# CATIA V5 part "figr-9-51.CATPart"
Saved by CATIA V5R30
Part number: Part1
Bounding box of the stored display mesh (mm): x -121 to 121, y -90 to 90, z -40 to 40
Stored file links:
  D:\PROJECTS\CATIA V56R 2020\Resources\Parts File\c09_catia_v5_6r2020_prt\figr-9-51.CATPart
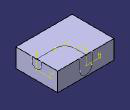
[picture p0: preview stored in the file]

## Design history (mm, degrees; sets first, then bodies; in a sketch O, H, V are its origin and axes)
Body1 (main body)
  Sketch1 on yz-plane, origin (0, 0, 0), H (0, 1, 0), V (0, 0, 1)
    line L1 (-90, 40) -> (90, 40)
    line L2 (90, 40) -> (90, -40)
    line L3 (90, -40) -> (-90, -40)
    line L4 (-90, -40) -> (-90, 40)
    axis line L5 (90, -40) -> (-90, 40)
    horizontal: L1 H, L3 H
    vertical: L2 V, L4 V
    midpoint: O L5
  Pad1: profile Sketch1, direction (1, 0, 0), length 121, mirrored extent
  Sketch2 on face of Pad1, origin (0, 0, 40), H (1, 0, 0), V (0, 1, 0)
    point P1 (121, 0)
    line L1 (121, 0) -> (40.984, 0)
    arc A1 centre (40.984, 40.984) radius 40.984 from (40.984, 0) to (0, 40.984) cw
    line L2 (0, 40.984) -> (0, 90)
    point P5 (0, 90)
    reference projected line E1 (121, 20) -> (121, -20) from edge of Sketch4
    reference projected line E2 (-25.9516, 90) -> (25.9516, 90) from edge of Sketch3
    coincidence: P1 H, P1 E1, P5 E2
    horizontal: L1 H
    tangency: A1 L1, L2 A1
    vertical: L2 V
  Sketch3 on face of Pad1, origin (0, 90, 0), H (-1, 0, 0), V (0, 0, 1)
    line L1 (-25.9516, 40) -> (-25.9516, -8.0968)
    arc A1 centre (0, -8.0968) radius 25.9516 from (-25.9516, -8.0968) to (25.9516, -8.0968) ccw
    point P3 (0, -8.0968)
    line L2 (25.9516, -8.0968) -> (25.9516, 40)
    line L3 (25.9516, 40) -> (-25.9516, 40)
    reference projected line E1 (121, 40) -> (-121, 40) from edge [face of Pad1 | face of Pad1]
    vertical: L1 V, L2 V
    tangency: A1 L1, L2 A1
    horizontal: L3 H
    coincidence: P3 V, L3 E1
  Sketch4 on face of Pad1, origin (121, 0, 0), H (0, 1, 0), V (0, 0, 1)
    line L1 (-20, 40) -> (-20, 21.9917)
    arc A1 centre (0, 21.9917) radius 20 from (-20, 21.9917) to (20, 21.9917) ccw
    point P3 (0, 21.9917)
    line L2 (20, 21.9917) -> (20, 40)
    line L3 (20, 40) -> (-20, 40)
    reference projected line E1 (90, 40) -> (-90, 40) from edge [face of Pad1 | face of Pad1]
    vertical: L1 V, L2 V
    tangency: A1 L1, L2 A1
    horizontal: L3 H
    coincidence: P3 V, L3 E1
